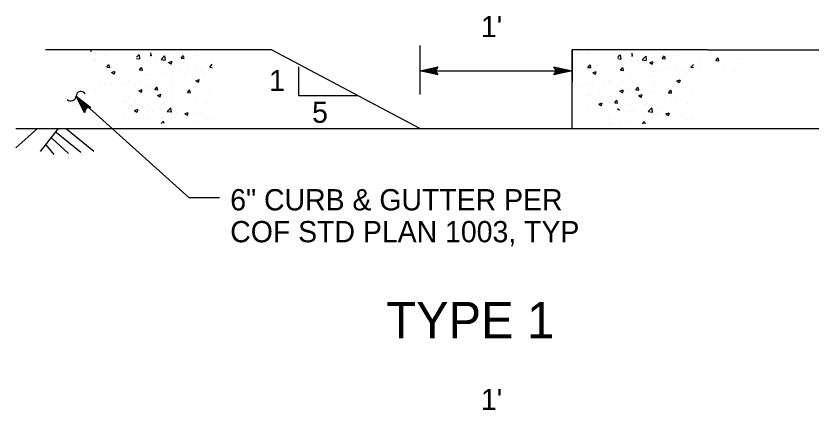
# Model space of a CAD drawing. Extents: x 6710407 to 6714861, y 1868090 to 1871317.
# Drawn here: x 6712811.5 to 6713073.3, y 1871187 to 1871316.8 of the extents above; entities that cross this region are included whole.
import ezdxf

# ---------------------------------------------------------------- set-up
doc = ezdxf.new("R2010")
doc.units = 0
doc.layers.add('Nongeo Data(60)', color=7, linetype='Continuous')

msp = doc.modelspace()

# ---------------------------------------------------------------- linework, layer by layer
at = {"layer": 'Nongeo Data(60)'}
for p, q in [((6712944.41, 1871307.02), (6712944.41, 1871290.9)), ((6712895.62, 1871305.68), (6712821.15, 1871305.68)), ((6712836, 1871305.18), (6712836.19, 1871305.15)), ((6712836.28, 1871305.08), (6712836.23, 1871305.45)), ((6712837.58, 1871304.36), (6712837.58, 1871304.36)), ((6712841.34, 1871304.85), (6712841.34, 1871304.85)), ((6712841.43, 1871304.24), (6712841.43, 1871304.24)), ((6712851.18, 1871303.2), (6712852.04, 1871304.09)), ((6712852.29, 1871302.6), (6712852.12, 1871304.03)), ((6712856.1, 1871303.68), (6712855.92, 1871304.62)), ((6712944.41, 1871279.71), (6712895.62, 1871305.68)), ((6712994.6, 1871305.68), (6712994.6, 1871295.23)), ((6712994.6, 1871279.71), (6712994.6, 1871305.68)), ((6713039.22, 1871305.68), (6712994.6, 1871305.68)), ((6712994.7, 1871305), (6712994.66, 1871305.36)), ((6712996.01, 1871304.27), (6712996.01, 1871304.27)), ((6712999.76, 1871304.77), (6712999.76, 1871304.77)), ((6712999.85, 1871304.16), (6712999.85, 1871304.16)), ((6713014.52, 1871303.59), (6713014.34, 1871304.53)), ((6713039.22, 1871305.68), (6713138.24, 1871305.68)), ((6712837.24, 1871302.7), (6712837.24, 1871302.7)), ((6712837.79, 1871302.06), (6712837.79, 1871302.06)), ((6712851.18, 1871302.82), (6712852.2, 1871302.66)), ((6712855.68, 1871303.77), (6712856.01, 1871303.74)), ((6712855.72, 1871302.51), (6712855.72, 1871302.51)), ((6712857.6, 1871302.06), (6712857.6, 1871302.06)), ((6712859.27, 1871302.47), (6712860.43, 1871303.68)), ((6712859.27, 1871302.47), (6712860.6, 1871302.26)), ((6712860.68, 1871302.2), (6712860.52, 1871303.62)), ((6712861.75, 1871301.52), (6712862.8, 1871301.92)), ((6712861.75, 1871301.52), (6712862.49, 1871301.02)), ((6712862.58, 1871300.96), (6712862.88, 1871301.86)), ((6712863.3, 1871303.47), (6712863.3, 1871303.47)), ((6712865.88, 1871302.88), (6712866.6, 1871303.74)), ((6712865.88, 1871302.88), (6712866.77, 1871302.8)), ((6712866.85, 1871302.74), (6712866.68, 1871303.68)), ((6712867.07, 1871303.31), (6712867.07, 1871303.31)), ((6712870.83, 1871303.8), (6712870.83, 1871303.8)), ((6712995.67, 1871302.62), (6712995.67, 1871302.62)), ((6712996.21, 1871301.97), (6712996.21, 1871301.97)), ((6713009.61, 1871303.11), (6713010.46, 1871304)), ((6713009.61, 1871302.74), (6713010.63, 1871302.58)), ((6713010.71, 1871302.52), (6713010.54, 1871303.94)), ((6713014.1, 1871303.68), (6713014.44, 1871303.65)), ((6713014.14, 1871302.42), (6713014.14, 1871302.42)), ((6713016.02, 1871301.97), (6713016.02, 1871301.97)), ((6713017.69, 1871302.38), (6713018.86, 1871303.6)), ((6713017.69, 1871302.38), (6713019.02, 1871302.17)), ((6713019.11, 1871302.11), (6713018.94, 1871303.54)), ((6713020.17, 1871301.43), (6713021.22, 1871301.84)), ((6713020.17, 1871301.43), (6713020.92, 1871300.93)), ((6713021, 1871300.87), (6713021.3, 1871301.78)), ((6713021.72, 1871303.38), (6713021.72, 1871303.38)), ((6713024.3, 1871302.79), (6713025.02, 1871303.65)), ((6713024.3, 1871302.79), (6713025.2, 1871302.71)), ((6713025.28, 1871302.65), (6713025.1, 1871303.59)), ((6713025.5, 1871303.22), (6713025.5, 1871303.22)), ((6713029.25, 1871303.72), (6713029.25, 1871303.72)), ((6713036.93, 1871302.5), (6713036.93, 1871302.5)), ((6713041.33, 1871303.2), (6713041.33, 1871303.2)), ((6713041.95, 1871302.12), (6713042.68, 1871302.98)), ((6713041.95, 1871302.12), (6713042.85, 1871302.04)), ((6713042.61, 1871303.24), (6713042.61, 1871303.24)), ((6713042.93, 1871301.98), (6713042.76, 1871302.92)), ((6713049.33, 1871302.86), (6713049.33, 1871302.86)), ((6712837.39, 1871298.94), (6712837.39, 1871298.94)), ((6712840.84, 1871299.41), (6712840.84, 1871299.41)), ((6712840.95, 1871300.04), (6712840.95, 1871300.04)), ((6712841.24, 1871299.25), (6712841.24, 1871299.25)), ((6712841.38, 1871299.95), (6712842.1, 1871300.81)), ((6712841.38, 1871299.95), (6712842.27, 1871299.87)), ((6712842.36, 1871299.81), (6712842.18, 1871300.75)), ((6712843.07, 1871299.68), (6712843.07, 1871299.68)), ((6712852.14, 1871299.01), (6712852.86, 1871299.87)), ((6712852.14, 1871299.01), (6712853.03, 1871298.93)), ((6712852.55, 1871300.93), (6712852.55, 1871300.93)), ((6712853.11, 1871298.87), (6712852.94, 1871299.81)), ((6712857.46, 1871298.96), (6712857.46, 1871298.96)), ((6712862.31, 1871300.64), (6712862.31, 1871300.64)), ((6712868.37, 1871299.42), (6712868.37, 1871299.42)), ((6712870.32, 1871300.3), (6712870.32, 1871300.3)), ((6712870.9, 1871299.6), (6712870.9, 1871299.6)), ((6712875.27, 1871299.98), (6712876.13, 1871300.88)), ((6712875.27, 1871299.98), (6712876.13, 1871299.85)), ((6712904.53, 1871300), (6712904.53, 1871290.62)), ((6712944.41, 1871298.71), (6712950.41, 1871300.04)), ((6712945.8, 1871298.71), (6712950.17, 1871299.68)), ((6712947.17, 1871298.7), (6712950, 1871299.33)), ((6712948.55, 1871298.7), (6712949.76, 1871298.97)), ((6712950.41, 1871300.04), (6712949.61, 1871298.71)), ((6712950.41, 1871300.04), (6712950.41, 1871300.04)), ((6712989.4, 1871298.71), (6712988.6, 1871300.05)), ((6712988.6, 1871300.05), (6712988.6, 1871300.05)), ((6712988.6, 1871300.05), (6712994.6, 1871298.71)), ((6712988.81, 1871299.69), (6712993.22, 1871298.71)), ((6712989.05, 1871299.33), (6712991.83, 1871298.71)), ((6712989.22, 1871298.98), (6712990.45, 1871298.71)), ((6712995.82, 1871298.85), (6712995.82, 1871298.85)), ((6712999.26, 1871299.32), (6712999.26, 1871299.32)), ((6712999.37, 1871299.96), (6712999.37, 1871299.96)), ((6712999.67, 1871299.16), (6712999.67, 1871299.16)), ((6712999.8, 1871299.87), (6713000.52, 1871300.73)), ((6712999.8, 1871299.87), (6713000.7, 1871299.79)), ((6713000.78, 1871299.73), (6713000.6, 1871300.67)), ((6713001.5, 1871299.6), (6713001.5, 1871299.6)), ((6713010.56, 1871298.93), (6713011.28, 1871299.79)), ((6713010.56, 1871298.93), (6713011.46, 1871298.85)), ((6713010.97, 1871300.85), (6713010.97, 1871300.85)), ((6713011.54, 1871298.79), (6713011.36, 1871299.73)), ((6713015.89, 1871298.87), (6713015.89, 1871298.87)), ((6713020.73, 1871300.55), (6713020.73, 1871300.55)), ((6713026.79, 1871299.33), (6713026.79, 1871299.33)), ((6713028.74, 1871300.21), (6713028.74, 1871300.21)), ((6713029.33, 1871299.52), (6713029.33, 1871299.52)), ((6713033.7, 1871299.9), (6713034.55, 1871300.79)), ((6713033.7, 1871299.9), (6713034.55, 1871299.77)), ((6713036.74, 1871299.02), (6713036.74, 1871299.02)), ((6713042.94, 1871299.9), (6713042.94, 1871299.9)), ((6713044.54, 1871300.14), (6713044.54, 1871300.14)), ((6712842.98, 1871298.19), (6712844.03, 1871298.59)), ((6712842.98, 1871298.19), (6712843.73, 1871297.69)), ((6712843.81, 1871297.63), (6712844.11, 1871298.53)), ((6712855.54, 1871297.52), (6712855.54, 1871297.52)), ((6712859.62, 1871297.91), (6712859.62, 1871297.91)), ((6712863.11, 1871298.48), (6712863.11, 1871298.48)), ((6712863.13, 1871297.39), (6712863.13, 1871297.39)), ((6712865.47, 1871298.62), (6712865.47, 1871298.62)), ((6712866.88, 1871297.88), (6712866.88, 1871297.88)), ((6712872.56, 1871298.63), (6712872.56, 1871298.63)), ((6712873.48, 1871298.28), (6712873.48, 1871298.28)), ((6712950.41, 1871297.37), (6712944.41, 1871298.71)), ((6712944.41, 1871298.71), (6712944.41, 1871298.71)), ((6712944.41, 1871298.71), (6712994.6, 1871298.71)), ((6712950.19, 1871297.72), (6712945.79, 1871298.7)), ((6712949.96, 1871298.08), (6712947.17, 1871298.7)), ((6712949.78, 1871298.43), (6712948.55, 1871298.7)), ((6712949.61, 1871298.71), (6712950.41, 1871297.37)), ((6712950.41, 1871297.37), (6712950.41, 1871297.37)), ((6712994.6, 1871298.71), (6712988.6, 1871297.38)), ((6712988.6, 1871297.38), (6712989.4, 1871298.71)), ((6712988.6, 1871297.38), (6712988.6, 1871297.38)), ((6712993.2, 1871298.7), (6712988.83, 1871297.73)), ((6712991.83, 1871298.71), (6712989.01, 1871298.08)), ((6712990.45, 1871298.71), (6712989.24, 1871298.44)), ((6712994.6, 1871298.71), (6712994.6, 1871298.71)), ((6713001.4, 1871298.1), (6713002.45, 1871298.51)), ((6713001.4, 1871298.1), (6713002.15, 1871297.6)), ((6713002.23, 1871297.54), (6713002.53, 1871298.45)), ((6713013.96, 1871297.43), (6713013.96, 1871297.43)), ((6713018.04, 1871297.83), (6713018.04, 1871297.83)), ((6713021.54, 1871298.39), (6713021.54, 1871298.39)), ((6713021.55, 1871297.3), (6713021.55, 1871297.3)), ((6713023.89, 1871298.54), (6713023.89, 1871298.54)), ((6713025.3, 1871297.8), (6713025.3, 1871297.8)), ((6713030.99, 1871298.55), (6713030.99, 1871298.55)), ((6713031.9, 1871298.2), (6713031.9, 1871298.2)), ((6713038.67, 1871297.33), (6713038.67, 1871297.33)), ((6713048.14, 1871298.57), (6713048.14, 1871298.57)), ((6712834.8, 1871294.43), (6712834.8, 1871294.43)), ((6712839.13, 1871293.77), (6712839.13, 1871293.77)), ((6712841.06, 1871294.26), (6712841.06, 1871294.26)), ((6712842.81, 1871294.09), (6712842.81, 1871294.09)), ((6712846.57, 1871294.16), (6712846.57, 1871294.16)), ((6712848.6, 1871295.02), (6712848.6, 1871295.02)), ((6712848.85, 1871295.38), (6712848.85, 1871295.38)), ((6712850.82, 1871293.75), (6712850.82, 1871293.75)), ((6712852.36, 1871295.51), (6712852.36, 1871295.51)), ((6712863.21, 1871294.62), (6712863.21, 1871294.62)), ((6712870.7, 1871295.48), (6712871.75, 1871295.88)), ((6712870.7, 1871295.48), (6712871.45, 1871294.98)), ((6712870.72, 1871294.61), (6712870.72, 1871294.61)), ((6712871.53, 1871294.92), (6712871.83, 1871295.82)), ((6712871.96, 1871296.12), (6712871.96, 1871296.12)), ((6712997.55, 1871293.68), (6712997.55, 1871293.68)), ((6712999.48, 1871294.17), (6712999.48, 1871294.17)), ((6713001.23, 1871294.01), (6713001.23, 1871294.01)), ((6713004.99, 1871294.07), (6713004.99, 1871294.07)), ((6713007.02, 1871294.93), (6713007.02, 1871294.93)), ((6713007.27, 1871295.29), (6713007.27, 1871295.29)), ((6713009.24, 1871293.67), (6713009.24, 1871293.67)), ((6713010.78, 1871295.42), (6713010.78, 1871295.42)), ((6713021.64, 1871294.53), (6713021.64, 1871294.53)), ((6713029.12, 1871295.4), (6713030.17, 1871295.8)), ((6713029.12, 1871295.4), (6713029.87, 1871294.89)), ((6713029.15, 1871294.52), (6713029.15, 1871294.52)), ((6713029.95, 1871294.83), (6713030.26, 1871295.74)), ((6713030.38, 1871296.04), (6713030.38, 1871296.04)), ((6712837.82, 1871292.66), (6712837.82, 1871292.66)), ((6712851.93, 1871292.15), (6712852.98, 1871292.55)), ((6712851.93, 1871292.15), (6712852.68, 1871291.65)), ((6712852.76, 1871291.59), (6712853.07, 1871292.49)), ((6712854.46, 1871293.12), (6712854.46, 1871293.12)), ((6712855.35, 1871292.52), (6712855.35, 1871292.52)), ((6712857.2, 1871292.54), (6712857.92, 1871293.4)), ((6712857.2, 1871292.54), (6712858.1, 1871292.46)), ((6712858.18, 1871292.4), (6712858, 1871293.34)), ((6712858.1, 1871290.64), (6712859.15, 1871291.05)), ((6712858.93, 1871290.08), (6712859.23, 1871290.99)), ((6712859.18, 1871291.47), (6712859.18, 1871291.47)), ((6712859.32, 1871293.01), (6712859.32, 1871293.01)), ((6712862.93, 1871293.48), (6712862.93, 1871293.48)), ((6712862.94, 1871291.97), (6712862.94, 1871291.97)), ((6712867.33, 1871292.67), (6712867.33, 1871292.67)), ((6712867.96, 1871291.59), (6712868.68, 1871292.46)), ((6712867.96, 1871291.59), (6712868.85, 1871291.52)), ((6712868.62, 1871292.72), (6712868.62, 1871292.72)), ((6712868.94, 1871291.46), (6712868.76, 1871292.4)), ((6712875.34, 1871292.33), (6712875.34, 1871292.33)), ((6712996.24, 1871292.57), (6712996.24, 1871292.57)), ((6713000.26, 1871291.02), (6713000.26, 1871291.02)), ((6713003.76, 1871291.14), (6713003.76, 1871291.14)), ((6713010.36, 1871292.06), (6713011.41, 1871292.47)), ((6713010.36, 1871292.06), (6713011.1, 1871291.56)), ((6713011.18, 1871291.5), (6713011.49, 1871292.41)), ((6713012.89, 1871293.03), (6713012.89, 1871293.03)), ((6713013.78, 1871292.44), (6713013.78, 1871292.44)), ((6713015.62, 1871292.45), (6713016.34, 1871293.31)), ((6713015.62, 1871292.45), (6713016.52, 1871292.37)), ((6713016.6, 1871292.31), (6713016.43, 1871293.25)), ((6713016.52, 1871290.56), (6713017.57, 1871290.96)), ((6713017.6, 1871291.39), (6713017.6, 1871291.39)), ((6713017.75, 1871292.93), (6713017.75, 1871292.93)), ((6713021.35, 1871293.4), (6713021.35, 1871293.4)), ((6713021.36, 1871291.88), (6713021.36, 1871291.88)), ((6713025.75, 1871292.59), (6713025.75, 1871292.59)), ((6713026.38, 1871291.51), (6713027.1, 1871292.37)), ((6713026.38, 1871291.51), (6713027.28, 1871291.43)), ((6713027.04, 1871292.63), (6713027.04, 1871292.63)), ((6713027.36, 1871291.37), (6713027.19, 1871292.31)), ((6713033.76, 1871292.25), (6713033.76, 1871292.25)), ((6712868.52, 1871256.91), (6712831.25, 1871290.43)), ((6712834.01, 1871284.94), (6712831.25, 1871290.43)), ((6712831.25, 1871290.43), (6712831.25, 1871290.43)), ((6712831.25, 1871290.43), (6712836.08, 1871286.63)), ((6712834.15, 1871285.33), (6712832.12, 1871289.36)), ((6712832.13, 1871289.36), (6712835.65, 1871286.59)), ((6712833.39, 1871290.44), (6712833.42, 1871290.47)), ((6712847.23, 1871288.51), (6712847.23, 1871288.51)), ((6712847.48, 1871288.88), (6712847.48, 1871288.88)), ((6712848.67, 1871290.39), (6712848.67, 1871290.39)), ((6712850.99, 1871289.01), (6712850.99, 1871289.01)), ((6712858.1, 1871290.64), (6712858.84, 1871290.14)), ((6712862.75, 1871288.49), (6712862.75, 1871288.49)), ((6712868.94, 1871289.37), (6712868.94, 1871289.37)), ((6712870.54, 1871289.61), (6712870.54, 1871289.61)), ((6712904.53, 1871290.62), (6712923.92, 1871290.62)), ((6712997.97, 1871289.79), (6712997.97, 1871289.79)), ((6713000.01, 1871290.65), (6713000.01, 1871290.65)), ((6713002.23, 1871289.39), (6713002.23, 1871289.39)), ((6713005.87, 1871288.75), (6713005.87, 1871288.75)), ((6713007.09, 1871290.3), (6713007.09, 1871290.3)), ((6713008.61, 1871288.17), (6713009.33, 1871289.03)), ((6713009.58, 1871288.03), (6713009.41, 1871288.97)), ((6713016.52, 1871290.56), (6713017.27, 1871290.05)), ((6713017.35, 1871289.99), (6713017.65, 1871290.9)), ((6713021.17, 1871288.4), (6713021.17, 1871288.4)), ((6713027.36, 1871289.29), (6713027.36, 1871289.29)), ((6713028.96, 1871289.53), (6713028.96, 1871289.53)), ((6712834.28, 1871285.74), (6712832.99, 1871288.29)), ((6712832.99, 1871288.29), (6712835.27, 1871286.5)), ((6712834.43, 1871286.1), (6712833.87, 1871287.22)), ((6712833.87, 1871287.22), (6712834.84, 1871286.46)), ((6712834.54, 1871286.41), (6712834.01, 1871284.94)), ((6712836.08, 1871286.63), (6712834.54, 1871286.41)), ((6712836.08, 1871286.63), (6712836.08, 1871286.63)), ((6712849.45, 1871287.25), (6712849.45, 1871287.25)), ((6712850.56, 1871285.65), (6712851.61, 1871286.05)), ((6712851.39, 1871285.08), (6712851.7, 1871285.99)), ((6712853.1, 1871286.61), (6712853.1, 1871286.61)), ((6712855.17, 1871287.53), (6712855.17, 1871287.53)), ((6712858.99, 1871286.05), (6712858.99, 1871286.05)), ((6712860.19, 1871287.87), (6712860.19, 1871287.87)), ((6712861.26, 1871285.37), (6712862.42, 1871286.59)), ((6712862.67, 1871285.1), (6712862.51, 1871286.53)), ((6712864.67, 1871286.8), (6712864.67, 1871286.8)), ((6712874.14, 1871288.05), (6712874.14, 1871288.05)), ((6713000.08, 1871286.02), (6713000.08, 1871286.02)), ((6713003.34, 1871287.79), (6713004.39, 1871288.19)), ((6713003.34, 1871287.79), (6713004.09, 1871287.28)), ((6713004.17, 1871287.22), (6713004.47, 1871288.13)), ((6713006.76, 1871288.16), (6713006.76, 1871288.16)), ((6713008.61, 1871288.17), (6713009.5, 1871288.09)), ((6713009.5, 1871286.28), (6713010.25, 1871285.77)), ((6713013.6, 1871287.44), (6713013.6, 1871287.44)), ((6713017.41, 1871285.97), (6713017.41, 1871285.97)), ((6713018.62, 1871287.78), (6713018.62, 1871287.78)), ((6713019.68, 1871285.29), (6713020.85, 1871286.5)), ((6713021.09, 1871285.02), (6713020.93, 1871286.44)), ((6713023.09, 1871286.71), (6713023.09, 1871286.71)), ((6713032.57, 1871287.96), (6713032.57, 1871287.96)), ((6712834.01, 1871284.94), (6712834.01, 1871284.94)), ((6712847.3, 1871283.88), (6712847.3, 1871283.88)), ((6712850.56, 1871285.65), (6712851.31, 1871285.14)), ((6712855.23, 1871285.56), (6712855.23, 1871285.56)), ((6712856.4, 1871285.35), (6712856.4, 1871285.35)), ((6712859.57, 1871283.33), (6712859.57, 1871283.33)), ((6712861.26, 1871285.37), (6712862.59, 1871285.17)), ((6712862.57, 1871283.5), (6712862.57, 1871283.5)), ((6712864.41, 1871285.01), (6712864.41, 1871285.01)), ((6712867.05, 1871284.6), (6712868.1, 1871285.01)), ((6712867.05, 1871284.6), (6712867.8, 1871284.1)), ((6712867.88, 1871284.04), (6712868.18, 1871284.95)), ((6712870.36, 1871284.62), (6712870.36, 1871284.62)), ((6712872.42, 1871284.67), (6712872.42, 1871284.67)), ((6713006.58, 1871283.16), (6713006.58, 1871283.16)), ((6713013.66, 1871285.47), (6713013.66, 1871285.47)), ((6713014.83, 1871285.26), (6713014.83, 1871285.26)), ((6713017.99, 1871283.25), (6713017.99, 1871283.25)), ((6713019.68, 1871285.29), (6713021.01, 1871285.08)), ((6713020.99, 1871283.41), (6713020.99, 1871283.41)), ((6713022.83, 1871284.92), (6713022.83, 1871284.92)), ((6713025.47, 1871284.52), (6713026.52, 1871284.92)), ((6713025.47, 1871284.52), (6713026.22, 1871284.01)), ((6713026.3, 1871283.95), (6713026.61, 1871284.86)), ((6713028.78, 1871284.54), (6713028.78, 1871284.54)), ((6713030.84, 1871284.58), (6713030.84, 1871284.58)), ((6712854.99, 1871282.54), (6712854.99, 1871282.54)), ((6712859.34, 1871281.33), (6712860, 1871282.11)), ((6712860.22, 1871281.33), (6712860.08, 1871282.05)), ((6712867.57, 1871282.99), (6712867.57, 1871282.99)), ((6712870.2, 1871282.13), (6712870.2, 1871282.13)), ((6712873.95, 1871282.63), (6712873.95, 1871282.63)), ((6712875.58, 1871282.65), (6712875.58, 1871282.65)), ((6713006.64, 1871281.19), (6713006.64, 1871281.19)), ((6713007.81, 1871280.98), (6713007.81, 1871280.98)), ((6713010.4, 1871281.69), (6713010.4, 1871281.69)), ((6713013.41, 1871282.45), (6713013.41, 1871282.45)), ((6713017.76, 1871281.24), (6713018.43, 1871282.03)), ((6713018.64, 1871281.24), (6713018.51, 1871281.97)), ((6713026, 1871282.91), (6713026, 1871282.91)), ((6713028.62, 1871282.05), (6713028.62, 1871282.05)), ((6713032.38, 1871282.54), (6713032.38, 1871282.54)), ((6713034, 1871282.57), (6713034, 1871282.57)), ((6712818.58, 1871279.73), (6712811.46, 1871273.39)), ((6712811.46, 1871279.71), (6712944.41, 1871279.71)), ((6712811.46, 1871279.71), (6712861.46, 1871279.71)), ((6712825.34, 1871279.68), (6712819.47, 1871272.21)), ((6712824.76, 1871278.56), (6712832.82, 1871271.93)), ((6712828.08, 1871279.65), (6712837.09, 1871272.24)), ((6712944.41, 1871279.71), (6713011.49, 1871279.71)), ((6712994.6, 1871279.71), (6713132.67, 1871279.71)), ((6712823.29, 1871276.5), (6712828.79, 1871271.49)), ((6712821.34, 1871274.35), (6712823.92, 1871271.19)), ((6712878.52, 1871256.91), (6712868.52, 1871256.91))]:
    msp.add_line(p, q, dxfattribs=at)
for centre, radius, start, end in [((6712832.87, 1871290.34), 1.62, 31.3389, 176.747), ((6712829.52, 1871290.53), 1.73, 227.6526, 356.747)]:
    msp.add_arc(centre, radius, start, end, dxfattribs=at)

# ---------------------------------------------------------------- texts
for s, height, p in [("1'", 7, (6712964.58, 1871309.81)), ('1', 7, (6712894.82, 1871292.04)), ('5', 7, (6712908.98, 1871281.61)), ('6" CURB & GUTTER PER', 7, (6712882.03, 1871252.77)), ('COF STD PLAN 1003, TYP', 7, (6712882.03, 1871242.27)), ('TYPE 1', 12, (6712933.41, 1871210.64)), ("1'", 7, (6712964.58, 1871187.01))]:
    msp.add_text(s, height=height, dxfattribs=at).set_placement(p)

doc.saveas('drawing.dxf')
